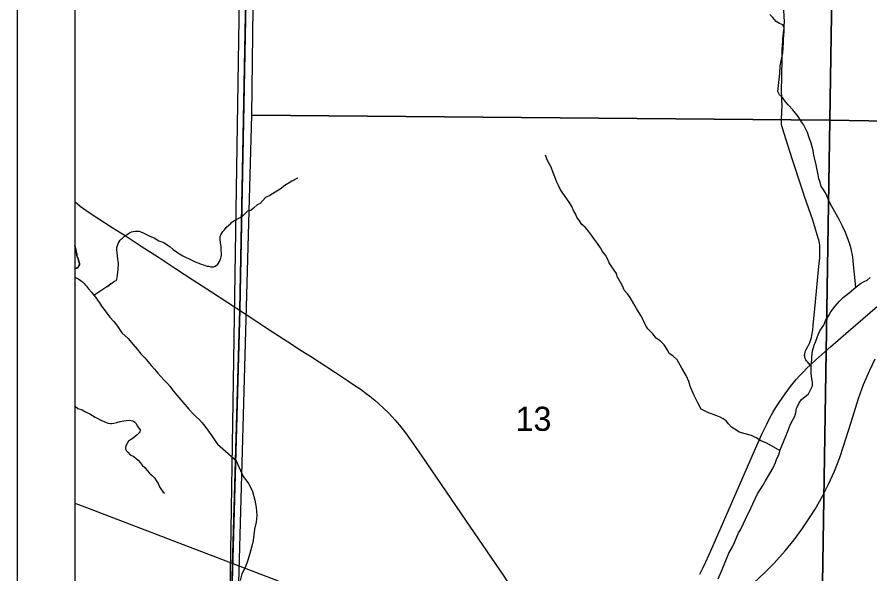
# Model space of a CAD drawing. Extents: x -1.2 to 34, y -8.5 to 22.
# Drawn here: x 2 to 3.48, y 14.86 to 15.827 of the extents above; entities that cross this region are included whole.
import ezdxf

# ---------------------------------------------------------------- set-up
doc = ezdxf.new("R2010")
doc.units = 0
for name, color, linetype in [('DV_X_County_Line', 7, 'Continuous'), ('GM_X_Major_River', 7, 'Continuous'), ('GM_X_Minor_Lake', 7, 'Continuous'), ('GM_X_Minor_River', 7, 'Continuous'), ('GM_X_Rail_Line', 7, 'Continuous'), ('GM_X_Section', 7, 'Continuous'), ('GM_X_Section_Text', 7, 'Continuous'), ('GM_X_State_Route', 7, 'Continuous'), ('GM_X_Township_Road', 7, 'Continuous'), ('GM_X_Unincorporated_Text', 7, 'Continuous'), ('GM_X_US_Route', 7, 'Continuous'), ('SH_Cut_Line', 7, 'Continuous'), ('SH_Data', 7, 'Continuous')]:
    doc.layers.add(name, color=color, linetype=linetype)

msp = doc.modelspace()

# ---------------------------------------------------------------- linework, layer by layer
at = {"layer": 'DV_X_County_Line'}
msp.add_line((2.3586, 14.1), (2.465, 20.9), dxfattribs=at)
at = {"layer": 'GM_X_Major_River'}
for points in [[(2.1, 15.375), (2.1014, 15.3746), (2.1048, 15.3731), (2.1071, 15.372), (2.1094, 15.3701), (2.1117, 15.3682), (2.1136, 15.3671), (2.1167, 15.3641), (2.1182, 15.3623), (2.1205, 15.3596), (2.124, 15.3551), (2.1294, 15.3491), (2.1333, 15.3442)], [(2.1333, 15.3442), (2.1368, 15.3401), (2.1399, 15.3356), (2.1433, 15.3307), (2.1468, 15.325), (2.1511, 15.319), (2.1557, 15.313), (2.1611, 15.3058), (2.1677, 15.2983), (2.1746, 15.29), (2.182, 15.2787), (2.1928, 15.269), (2.2009, 15.2588), (2.2086, 15.2502), (2.2151, 15.2423), (2.2217, 15.2352), (2.2275, 15.2284), (2.2329, 15.222), (2.2387, 15.2153), (2.2445, 15.2085), (2.2498, 15.2029), (2.2549, 15.1972), (2.2614, 15.1905), (2.266, 15.1852), (2.2711, 15.1781), (2.2776, 15.1702), (2.2842, 15.1623), (2.2911, 15.154), (2.2981, 15.1461), (2.305, 15.1386), (2.3111, 15.1326), (2.3165, 15.1274), (2.3215, 15.1225), (2.3262, 15.1165), (2.3382, 15.0999), (2.3428, 15.0928), (2.3479, 15.0852), (2.3808, 15.0562)], [(2.3805, 15.0565), (2.3924, 15.029), (2.4024, 15.0166), (2.4089, 15.0033), (2.4128, 14.9878), (2.4148, 14.9753), (2.416, 14.9613), (2.415, 14.9495), (2.4121, 14.9374), (2.411, 14.9275), (2.4096, 14.918), (2.4074, 14.9081), (2.4041, 14.8952), (2.4001, 14.8819), (2.3964, 14.8724), (2.39, 14.8598), (2.3871, 14.8484)]]:
    msp.add_lwpolyline(points, dxfattribs=at)
at = {"layer": 'GM_X_Minor_Lake'}
for points in [[(2.1, 15.3903), (2.1012, 15.3901), (2.1038, 15.3909), (2.1061, 15.3929), (2.1075, 15.3948), (2.1083, 15.3967), (2.1086, 15.399), (2.1078, 15.4009), (2.107, 15.4031), (2.1066, 15.405), (2.1062, 15.4069), (2.1051, 15.4099), (2.1039, 15.4126), (2.1035, 15.4156), (2.1027, 15.419), (2.1018, 15.4239), (2.1006, 15.4274), (2.1, 15.4304)], [(2.1, 15.4304), (2.1006, 15.4274), (2.1018, 15.4239), (2.1027, 15.419), (2.1035, 15.4156), (2.1039, 15.4126), (2.1051, 15.4099), (2.1062, 15.4069), (2.1066, 15.405), (2.107, 15.4031), (2.1078, 15.4009), (2.1086, 15.399), (2.1083, 15.3967), (2.1075, 15.3948), (2.1061, 15.3929), (2.1038, 15.3909), (2.1012, 15.3901), (2.1, 15.3903)]]:
    msp.add_lwpolyline(points, dxfattribs=at)
at = {"layer": 'GM_X_Minor_River'}
for points in [[(3.4558, 15.3581), (3.4512, 15.4032), (3.4507, 15.4104), (3.4478, 15.4248), (3.4455, 15.4328), (3.4407, 15.4453), (3.4376, 15.4532), (3.4329, 15.4642), (3.4267, 15.4755), (3.4193, 15.4887), (3.4115, 15.5031), (3.4033, 15.522), (3.3994, 15.528), (3.3955, 15.5329), (3.3939, 15.5405), (3.3916, 15.5462), (3.3903, 15.553), (3.3867, 15.5704), (3.383, 15.5875), (3.3817, 15.5951), (3.3785, 15.608), (3.3742, 15.619), (3.3718, 15.6269), (3.3652, 15.6405), (3.3617, 15.6454), (3.3559, 15.6545), (3.3466, 15.6661), (3.3386, 15.6748), (3.3324, 15.6815), (3.3285, 15.6872), (3.3235, 15.692), (3.3204, 15.6977), (3.3238, 15.729), (3.3243, 15.7423), (3.3293, 15.7648), (3.3302, 15.7831), (3.3305, 15.7884), (3.3314, 15.8029), (3.3317, 15.8083), (3.329, 15.8139), (3.3232, 15.8157), (3.3175, 15.8195), (3.3117, 15.8262), (3.3064, 15.8315)], [(3.3242, 15.0738), (3.3013, 15.0869), (3.2911, 15.0909), (3.2826, 15.0965), (3.2746, 15.1002), (3.264, 15.1034), (3.2533, 15.1063), (3.2476, 15.11), (3.2403, 15.1145), (3.235, 15.1205), (3.2307, 15.1258), (3.2254, 15.1291), (3.2204, 15.1321), (3.2147, 15.1343), (3.1991, 15.1405), (3.1876, 15.146), (3.1818, 15.157), (3.1744, 15.171), (3.1693, 15.1831), (3.1677, 15.188), (3.1665, 15.1929), (3.1614, 15.2046), (3.154, 15.2175), (3.1455, 15.2318), (3.1382, 15.2389), (3.1321, 15.243), (3.1297, 15.2479), (3.1232, 15.2577), (3.1162, 15.2648), (3.109, 15.2693), (3.1036, 15.2768), (3.0947, 15.2854), (3.092, 15.2903), (3.0889, 15.2956), (3.0862, 15.3024), (3.0827, 15.3085), (3.0788, 15.3149), (3.0753, 15.3209), (3.0706, 15.3288), (3.0644, 15.3402), (3.0594, 15.3466), (3.054, 15.3526), (3.0509, 15.3601), (3.0415, 15.3767), (3.0403, 15.3817), (3.0322, 15.393), (3.0279, 15.4001), (3.0248, 15.4073), (3.0213, 15.4133), (3.0163, 15.4197), (3.0128, 15.4265), (3.0074, 15.4341), (3.0023, 15.4408), (2.9973, 15.4484), (2.9919, 15.4551), (2.9858, 15.4619), (2.98, 15.4671), (2.9761, 15.4732), (2.9715, 15.4796), (2.9695, 15.4852), (2.966, 15.4909), (2.9629, 15.4981), (2.9582, 15.5056), (2.9474, 15.5214), (2.9424, 15.5282), (2.9396, 15.5347), (2.9369, 15.5403), (2.9334, 15.5498), (2.931, 15.5555), (2.9267, 15.5676), (2.9216, 15.5759), (2.9197, 15.5808), (2.9173, 15.5872)], [(2.4866, 15.5471), (2.4772, 15.542), (2.4723, 15.5393), (2.4648, 15.5346), (2.4566, 15.5284), (2.448, 15.5229), (2.439, 15.5174), (2.4311, 15.5135), (2.4221, 15.5031), (2.4169, 15.5011), (2.4105, 15.4949), (2.4057, 15.4914), (2.4, 15.4898), (2.3913, 15.4812)], [(2.1333, 15.3442), (2.1626, 15.3639), (2.157, 15.3589), (2.1626, 15.3639), (2.169, 15.3682), (2.172, 15.3698), (2.1731, 15.3721), (2.1735, 15.3743), (2.1742, 15.3789), (2.1749, 15.3838), (2.1752, 15.388), (2.1755, 15.3918), (2.1758, 15.396), (2.1758, 15.3998), (2.1754, 15.4025), (2.1749, 15.407), (2.1745, 15.4123), (2.1736, 15.418), (2.1732, 15.4229), (2.1731, 15.4271), (2.1753, 15.434), (2.1772, 15.4367), (2.179, 15.4397), (2.1813, 15.4417), (2.1832, 15.4432), (2.1865, 15.4463), (2.1888, 15.4482), (2.191, 15.4494), (2.1933, 15.4513), (2.1952, 15.4521), (2.1986, 15.454), (2.2016, 15.4548), (2.2054, 15.4553), (2.2073, 15.4553), (2.2099, 15.4553), (2.2122, 15.455), (2.2149, 15.4542), (2.2187, 15.4524), (2.2237, 15.4498), (2.2306, 15.4468), (2.2382, 15.4435), (2.2458, 15.4387), (2.255, 15.4354), (2.2604, 15.4316), (2.2657, 15.4279), (2.2711, 15.4234), (2.2765, 15.4193), (2.2822, 15.4156), (2.288, 15.4126), (2.2933, 15.4096), (2.299, 15.4071), (2.3036, 15.4048), (2.309, 15.4022), (2.3155, 15.3997), (2.3197, 15.3982), (2.3235, 15.3967), (2.3265, 15.3956), (2.3296, 15.3945), (2.3326, 15.3942), (2.3357, 15.3935), (2.3391, 15.3931), (2.3414, 15.3932), (2.344, 15.3947), (2.3459, 15.3959), (2.3478, 15.397), (2.3515, 15.4028), (2.3526, 15.4054), (2.3537, 15.4081), (2.3544, 15.4108), (2.3547, 15.4134), (2.3547, 15.4169), (2.3542, 15.4218), (2.3542, 15.4279), (2.3533, 15.4358), (2.3528, 15.4408), (2.3524, 15.4438), (2.3528, 15.4465), (2.3539, 15.4491), (2.3554, 15.4518), (2.3572, 15.4545), (2.3602, 15.4576), (2.3632, 15.4614), (2.3673, 15.4656), (2.3707, 15.468), (2.3729, 15.4706), (2.3763, 15.473), (2.3915, 15.4813)], [(3.3575, 15.157), (3.3616, 15.1628), (3.3739, 15.1729), (3.3776, 15.1809), (3.3805, 15.1863), (3.3804, 15.1928), (3.3796, 15.1985), (3.3783, 15.2083), (3.3785, 15.2232), (3.3795, 15.232), (3.3794, 15.2369), (3.3808, 15.2472), (3.3833, 15.2571), (3.3862, 15.264), (3.3891, 15.2721), (3.3931, 15.282), (3.4002, 15.292), (3.4035, 15.3012), (3.4087, 15.3085), (3.4123, 15.3154), (3.4198, 15.3251), (3.4276, 15.3336), (3.4339, 15.3398), (3.444, 15.3483), (3.4556, 15.358), (3.4639, 15.3642), (3.4691, 15.3673), (3.4755, 15.3701), (3.4808, 15.3747)], [(2.1, 15.1518), (2.1006, 15.1513), (2.1056, 15.1471), (2.1129, 15.1446), (2.1178, 15.142), (2.1224, 15.1398), (2.1266, 15.1379), (2.1308, 15.1353), (2.1358, 15.1323), (2.1412, 15.129), (2.1465, 15.1264), (2.1511, 15.1245), (2.1549, 15.1231), (2.1583, 15.1216), (2.1618, 15.1209), (2.1641, 15.1209), (2.1682, 15.1217), (2.1731, 15.1229), (2.1792, 15.1245), (2.1852, 15.1257), (2.1902, 15.1266), (2.1947, 15.127), (2.1978, 15.1266), (2.2004, 15.1259), (2.2023, 15.1252), (2.2042, 15.1233), (2.2066, 15.1211), (2.2085, 15.1173), (2.2112, 15.1131), (2.2135, 15.1101), (2.2132, 15.106), (2.2087, 15.1017), (2.2016, 15.0959), (2.1967, 15.0928), (2.1937, 15.0905), (2.1889, 15.0825), (2.1882, 15.0794), (2.1882, 15.0772), (2.1901, 15.0738), (2.1924, 15.0715), (2.1963, 15.067), (2.2028, 15.0637), (2.207, 15.0603), (2.2105, 15.0569), (2.2139, 15.0532), (2.2174, 15.049), (2.2217, 15.0445), (2.2259, 15.0397), (2.2301, 15.0351), (2.2347, 15.0306), (2.2386, 15.0265), (2.2413, 15.0224), (2.2448, 15.0167), (2.2475, 15.0114), (2.2506, 15.0058), (2.2537, 15.0016), (2.2557, 15.0001)], [(3.2166, 14.8511), (3.2224, 14.8645), (3.229, 14.8802), (3.2352, 14.8959), (3.2419, 14.9067), (3.2455, 14.9144), (3.2521, 14.9312), (3.2554, 14.9366), (3.261, 14.9477), (3.2679, 14.9627), (3.2705, 14.9677), (3.2768, 14.9815), (3.2852, 14.9987), (3.2945, 15.0133), (3.2993, 15.0218), (3.3063, 15.0344), (3.3126, 15.0444), (3.3166, 15.0532), (3.3188, 15.0605), (3.3224, 15.067), (3.3246, 15.0754), (3.3301, 15.0892), (3.3356, 15.1019), (3.3432, 15.121), (3.3491, 15.1325), (3.3513, 15.1375), (3.3527, 15.1471), (3.3575, 15.157)]]:
    msp.add_lwpolyline(points, dxfattribs=at)
at = {"layer": 'GM_X_Rail_Line'}
for points in [[(3.2787, 14.8443), (3.2972, 14.8616), (3.314, 14.8785), (3.3329, 14.9), (3.3485, 14.9189), (3.3625, 14.938), (3.3743, 14.9555), (3.385, 14.9724), (3.398, 14.9949), (3.4084, 15.016), (3.4187, 15.0385), (3.4282, 15.0623), (3.4346, 15.0818), (3.4478, 15.1235), (3.4607, 15.1648), (3.4694, 15.1886), (3.4799, 15.2138), (3.4895, 15.2336)], [(2.1, 14.983), (2.113, 14.978), (2.2143, 14.9393), (2.3745, 14.8781)], [(2.3745, 14.8781), (2.4533, 14.8478)]]:
    msp.add_lwpolyline(points, dxfattribs=at)
at = {"layer": 'GM_X_Section'}
for points in [[(3.4269, 16.668), (3.4107, 15.6483), (2.4074, 15.6568), (2.4204, 16.684)], [(3.4269, 16.668), (4.4375, 16.6421), (4.4223, 15.6306), (3.4107, 15.6483)], [(3.4107, 15.6483), (3.3946, 14.624), (2.3794, 14.636), (2.4074, 15.6568)], [(3.4107, 15.6483), (4.4223, 15.6306), (4.409, 14.6166), (3.3946, 14.624)]]:
    msp.add_lwpolyline(points, close=True, dxfattribs=at)
at = {"layer": 'GM_X_State_Route'}
msp.add_lwpolyline([(3.1848, 14.8593), (3.188, 14.8653), (3.1909, 14.8711), (3.1954, 14.8807), (3.2061, 14.904), (3.2124, 14.9184), (3.2816, 15.0777), (3.2927, 15.1027), (3.2965, 15.1108), (3.3011, 15.1201), (3.3068, 15.1309), (3.312, 15.1403), (3.3172, 15.1491), (3.3226, 15.1577), (3.3278, 15.1654), (3.3331, 15.1729), (3.3426, 15.1854), (3.3473, 15.1914), (3.3523, 15.1973), (3.3582, 15.2039), (3.3636, 15.2096), (3.3709, 15.217), (3.3767, 15.2227), (3.3864, 15.2319), (3.4118, 15.2543), (3.4385, 15.2772), (3.6326, 15.4453)], dxfattribs=at)
at = {"layer": 'GM_X_Township_Road'}
for points in [[(3.3274, 15.6383), (3.327, 15.6404), (3.3266, 15.6436), (3.3267, 15.6496), (3.3268, 15.6524), (3.3273, 15.6589), (3.3276, 15.6653), (3.3277, 15.6713), (3.3269, 15.6999), (3.3268, 15.7044), (3.3272, 15.7181), (3.3275, 15.7255), (3.3277, 15.7542), (3.3279, 15.7631), (3.328, 15.7706), (3.3283, 15.7782), (3.3289, 15.7867), (3.3291, 15.7895), (3.3313, 15.8082), (3.3317, 15.8125), (3.3319, 15.8191), (3.3282, 15.8891)], [(3.3736, 15.2572), (3.3749, 15.2595), (3.3759, 15.2617), (3.3772, 15.2654), (3.3787, 15.2704), (3.3796, 15.274), (3.3806, 15.2801), (3.381, 15.283), (3.3818, 15.2912), (3.3857, 15.3327), (3.3911, 15.3879), (3.3922, 15.3991), (3.3932, 15.4088), (3.3936, 15.4158), (3.3936, 15.4262), (3.3932, 15.4312), (3.3927, 15.4342), (3.3914, 15.4403), (3.3907, 15.4429), (3.3829, 15.4685), (3.3809, 15.4744), (3.367, 15.5156), (3.3651, 15.5211), (3.3599, 15.5369), (3.3472, 15.5759), (3.3413, 15.5936), (3.3342, 15.6156), (3.3289, 15.6325), (3.3278, 15.6363), (3.3274, 15.6383)], [(3.3767, 15.2227), (3.3743, 15.2253), (3.3717, 15.2281), (3.3703, 15.2299), (3.369, 15.232), (3.3681, 15.2339), (3.3674, 15.2359), (3.3671, 15.2376), (3.367, 15.2395), (3.3673, 15.2423), (3.3677, 15.2447), (3.3683, 15.2472), (3.3689, 15.2487), (3.3694, 15.2497), (3.3723, 15.2549), (3.3736, 15.2572)]]:
    msp.add_lwpolyline(points, dxfattribs=at)
at = {"layer": 'GM_X_Unincorporated_Text'}
for p, q in [((2.1, 20.6871), (2.1, 14.6393)), ((2.402, 16.1209), (2.3867, 15.3183)), ((2.3867, 15.3183), (2.402, 16.1209)), ((2.3867, 15.3183), (2.3672, 14.6322)), ((2.3672, 14.6322), (2.3867, 15.3183))]:
    msp.add_line(p, q, dxfattribs=at)
at = {"layer": 'GM_X_US_Route'}
for points in [[(2.1, 15.5065), (2.1093, 15.4989), (2.1252, 15.4876), (2.1402, 15.4776), (2.1649, 15.4618), (2.1874, 15.4475), (2.2156, 15.4293), (2.2455, 15.4098), (2.2748, 15.3905), (2.3053, 15.3707), (2.3375, 15.3497), (2.3942, 15.3126)], [(2.3942, 15.3126), (2.409, 15.303), (2.4284, 15.2904), (2.4435, 15.2806), (2.4629, 15.2678), (2.474, 15.2606), (2.4905, 15.2499), (2.5092, 15.2379), (2.5529, 15.2095), (2.5733, 15.196), (2.5881, 15.1861), (2.5971, 15.1801), (2.6061, 15.1735), (2.6124, 15.1685), (2.6211, 15.1614), (2.6281, 15.1552), (2.6353, 15.1485), (2.6461, 15.1385), (2.6558, 15.1277), (2.6638, 15.1181), (2.6743, 15.1049), (2.692, 15.0796), (2.7026, 15.0643), (2.7188, 15.0404)], [(2.7188, 15.0404), (2.7362, 15.015), (2.7785, 14.9532), (2.8448, 14.8562), (2.8625, 14.8288), (2.8668, 14.8212), (2.8717, 14.8123), (2.8753, 14.8052), (2.8806, 14.7947), (2.893, 14.7664), (2.8986, 14.7529)]]:
    msp.add_lwpolyline(points, dxfattribs=at)
at = {"layer": 'SH_Cut_Line'}
msp.add_lwpolyline([(2.465, 20.9), (2.1, 20.9), (2.1, 14.1), (2.3586, 14.1), (2.3643, 14.4203), (2.3672, 14.6322), (2.3867, 15.3183), (2.402, 16.1209), (2.4189, 17.3824), (2.4258, 17.6899), (2.4414, 19.0677), (2.4628, 20.1657), (2.4644, 20.6742)], close=True, dxfattribs=at)
msp.add_lwpolyline([(4.6867, 17.6371), (4.4093, 17.6489), (4.1759, 17.654), (3.3984, 17.6707), (2.8968, 17.6806), (2.4258, 17.6899), (2.4189, 17.3824), (2.402, 16.1209), (2.3867, 15.3183), (2.3672, 14.6322), (2.3643, 14.4203), (2.3586, 14.1), (8.9, 14.1)], dxfattribs=at)
at = {"layer": 'SH_Data'}
for p, q in [((2, 21), (2, 14)), ((2, 21), (2, 14)), ((2.1, 20.9), (2.1, 14.1)), ((2.1, 20.9), (2.1, 14.1))]:
    msp.add_line(p, q, dxfattribs=at)

# ---------------------------------------------------------------- texts
at = {"layer": 'GM_X_Section_Text'}
msp.add_text('13', height=0.04186, rotation=0, dxfattribs=at).set_placement((2.8652, 15.1084))

doc.saveas('drawing.dxf')
